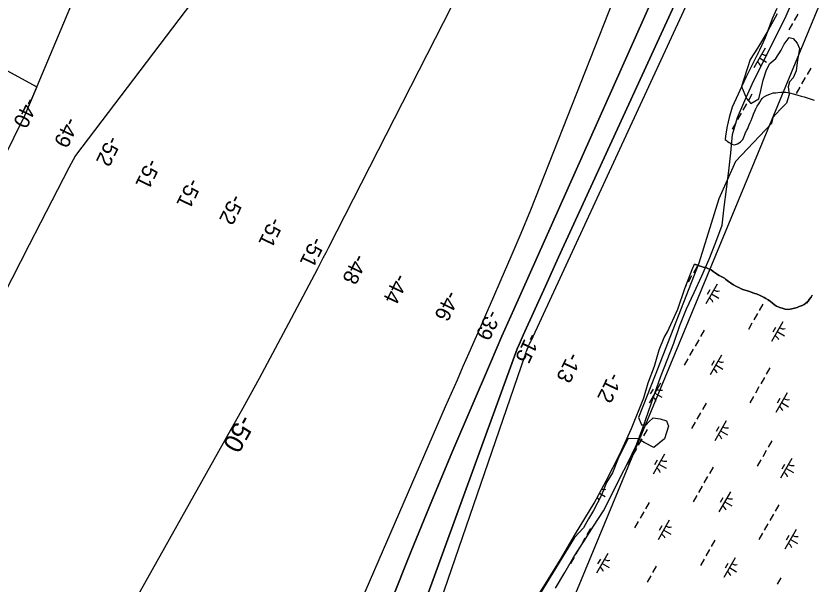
# Model space of a CAD drawing. Extents: x 3930721 to 3950824, y 220441 to 242861.
# Drawn here: x 3938420 to 3940167, y 225003 to 226251 of the extents above; entities that cross this region are included whole.
import ezdxf

# ---------------------------------------------------------------- set-up
doc = ezdxf.new("R2010")
doc.units = 0
for name, color, linetype in [('V-RIVR-EDGE', 7, 'Continuous'), ('V-RIVR-RANG', 7, 'Continuous'), ('V-RRAP-FSHR', 7, 'Continuous'), ('V-TOPO-DPTH', 7, 'Continuous'), ('V-TOPO-MAJR', 7, 'Continuous'), ('V-TOPO-MAJR-IDEN', 7, 'Continuous'), ('V-TOPO-MINR', 7, 'Continuous'), ('V-TOPO-SHOR', 7, 'Continuous'), ('V-UTIL-LINE', 7, 'Continuous'), ('V-WETL-SWMP', 7, 'Continuous')]:
    doc.layers.add(name, color=color, linetype=linetype)

msp = doc.modelspace()

# ---------------------------------------------------------------- linework, layer by layer
at = {"layer": 'V-RIVR-EDGE'}
msp.add_lwpolyline([(3940090.5, 226255.7), (3940070, 226217.9), (3940047.2, 226180.1), (3940031.4, 226154.9), (3940012.5, 226095.9), (3940023.6, 226069.9), (3940033, 226058.9), (3940050.3, 226069.1), (3940055, 226087.2), (3940059.8, 226110), (3940066.9, 226132.9), (3940074.7, 226146.3), (3940087.3, 226157.3), (3940099.1, 226175.4), (3940106.2, 226188.8), (3940117.2, 226203.7), (3940125.9, 226201.4), (3940134.5, 226191.1), (3940139.3, 226179.3), (3940134.5, 226148.6), (3940132.2, 226130.5), (3940125.9, 226114.8), (3940118, 226106.1), (3940114.9, 226095.1), (3940117.2, 226078.6), (3940110.9, 226059.7), (3940096.8, 226045.5), (3940081, 226028.2), (3940077.9, 226014.8), (3939999.2, 225931.4), (3939962.2, 225849.5), (3939918.9, 225707.8), (3939822.8, 225462.2), (3939786.6, 225369.3), (3939792.9, 225352.8), (3939803.2, 225352.8), (3939808.7, 225359.9), (3939818.1, 225368.5), (3939833.9, 225366.2), (3939848, 225361.5), (3939852, 225350.4), (3939843.3, 225322.1), (3939819.7, 225303.2), (3939798.4, 225314.2), (3939785.8, 225322.1), (3939763.8, 225322.9), (3939741.8, 225278.8), (3939729.2, 225247.3), (3939715.8, 225226.1), (3939704, 225196.9), (3939687.4, 225164.7), (3939676.4, 225146.6), (3939665.4, 225126.9), (3939645.7, 225105.6), (3939564.6, 224973.4)], dxfattribs=at)
at = {"layer": 'V-RRAP-FSHR'}
msp.add_lwpolyline([(3939604.4, 224994.7), (3939624.4, 225028.7), (3939644.5, 225063.3), (3939666.1, 225096.9), (3939687.8, 225130.6), (3939709.4, 225164.2), (3939727.8, 225199.7), (3939745.5, 225235.6), (3939763.2, 225271.4), (3939781, 225307.3), (3939795.2, 225344.6), (3939808.4, 225382.4), (3939821.6, 225420.1), (3939834.7, 225457.9), (3939848.9, 225495.3), (3939864, 225532.7), (3939877.3, 225570.8), (3939891.7, 225607.4), (3939908.3, 225643.8), (3939925, 225680.1), (3939941.2, 225716.7), (3939955.6, 225754.1), (3939969.6, 225791.4), (3939974.6, 225831.1), (3939979.5, 225870.8), (3939984.4, 225910.5), (3939988.8, 225950.3), (3939992.5, 225990.8), (3940003.7, 226028.2), (3940019.3, 226064.9), (3940035.5, 226101.4), (3940053.4, 226137.2), (3940071.4, 226172.9), (3940089.3, 226208.7), (3940107.2, 226244.4), (3940123.5, 226281)], dxfattribs=at)
at = {"layer": 'V-TOPO-DPTH'}
for points in [[(3938800.3, 226891.8), (3938439, 226031.3), (3937974.2, 225089.4)], [(3939105.4, 224799.2), (3939362.9, 225393), (3939375.8, 225422.6), (3939388.7, 225452.2), (3939401.6, 225481.7), (3939414.6, 225511.3), (3939427.6, 225540.8), (3939440.6, 225570.3), (3939453.5, 225599.9), (3939466.5, 225629.4), (3939485.1, 225671.9), (3939507.1, 225722.9), (3939528.6, 225774), (3939549.7, 225825.3), (3939570.3, 225876.8), (3939810.4, 226486.5)], [(3939105.4, 224799.2), (3939362.9, 225393), (3939375.8, 225422.6), (3939388.7, 225452.2), (3939401.6, 225481.7), (3939414.6, 225511.3), (3939427.6, 225540.8), (3939440.6, 225570.3), (3939453.5, 225599.9), (3939466.5, 225629.4), (3939485.1, 225671.9), (3939507.1, 225722.9), (3939528.6, 225774), (3939549.7, 225825.3), (3939570.3, 225876.8), (3939810.4, 226486.5)], [(3939914.9, 226384.5), (3939698.1, 225912.3), (3939668.9, 225848.7), (3939639.8, 225785), (3939610.7, 225721.2), (3939581.8, 225657.4), (3939533, 225549.7), (3939528.5, 225539.8), (3939524, 225529.8), (3939519.7, 225519.7), (3939183.5, 224595.7), (3939172.7, 224570.5), (3939161.8, 224545.3), (3938861.8, 223862.2), (3938847, 223828.5), (3938832.2, 223794.8), (3938819, 223764.4)], [(3938766.8, 223792.5), (3938950.3, 224222), (3938978.7, 224289.3), (3939006.6, 224356.7), (3939033.9, 224424.4), (3939060.9, 224492.3), (3939085.7, 224556), (3939099.8, 224592.2), (3939113.9, 224628.4), (3939127.8, 224664.7), (3939141.8, 224701), (3939199.5, 224852.2), (3939242.9, 224963.9), (3939287.2, 225075.3), (3939332.7, 225186.1), (3939379.1, 225296.5), (3939461.4, 225489.5), (3939474, 225518.8), (3939486.6, 225548), (3939499.4, 225577.1), (3939512.3, 225606.2), (3939815.8, 226284.8)], [(3939815.8, 226284.8), (3939512.3, 225606.2), (3939499.4, 225577.1), (3939486.6, 225548), (3939474, 225518.8), (3939461.4, 225489.5), (3939379.1, 225296.5), (3939332.7, 225186.1), (3939287.2, 225075.3), (3939242.9, 224963.9), (3939199.5, 224852.2), (3939141.8, 224701), (3939127.8, 224664.7), (3939113.9, 224628.4), (3939099.8, 224592.2), (3939085.7, 224556), (3939060.9, 224492.3), (3939033.9, 224424.4), (3939006.6, 224356.7), (3938978.7, 224289.3), (3938950.3, 224222), (3938766.8, 223792.5)], [(3938372.1, 226089.8), (3938383.8, 226098.3), (3938393.5, 226111.8), (3938400.2, 226131.1), (3938466, 226095.5)], [(3938466, 226095.5), (3938439, 226031.3), (3937974.2, 225089.4), (3937855.6, 224787.7), (3937817.1, 224692.8), (3937777.4, 224598.4), (3937735.8, 224504.8), (3937692.9, 224411.8), (3937676.9, 224378)]]:
    msp.add_lwpolyline(points, dxfattribs=at)
at = {"layer": 'V-TOPO-MAJR'}
for points in [[(3939076.2, 226636.5), (3938550.3, 225944.2), (3938535.9, 225917), (3938448.9, 225748.2), (3938391.7, 225636.2)], [(3938237.8, 224076.7), (3938466.6, 224557.2), (3938489.6, 224604.6), (3938512.9, 224651.9), (3938536.7, 224699), (3938560.8, 224745.8), (3938572.8, 224768.7), (3938591.4, 224803.9), (3938610.2, 224839), (3938629.3, 224873.9), (3938648.6, 224908.7), (3938882, 225325), (3938918.3, 225390.3), (3938954.3, 225455.8), (3938989.7, 225521.6), (3939024.8, 225587.5), (3939082.3, 225696.6), (3939088.4, 225708.2), (3939094.4, 225719.7), (3939100.4, 225731.3), (3939106.3, 225742.9), (3939376.3, 226272.7)]]:
    msp.add_lwpolyline(points, dxfattribs=at)
at = {"layer": 'V-TOPO-MINR'}
for points in [[(3938800.3, 226891.8), (3938439, 226031.3), (3937974.2, 225089.4)], [(3939105.4, 224799.2), (3939362.9, 225393), (3939375.8, 225422.6), (3939388.7, 225452.2), (3939401.6, 225481.7), (3939414.6, 225511.3), (3939427.6, 225540.8), (3939440.6, 225570.3), (3939453.5, 225599.9), (3939466.5, 225629.4), (3939485.1, 225671.9), (3939507.1, 225722.9), (3939528.6, 225774), (3939549.7, 225825.3), (3939570.3, 225876.8), (3939810.4, 226486.5)], [(3938819, 223764.4), (3938832.2, 223794.8), (3938847, 223828.5), (3938861.8, 223862.2), (3939161.8, 224545.3), (3939172.7, 224570.5), (3939183.5, 224595.7), (3939519.7, 225519.7), (3939524, 225529.8), (3939528.5, 225539.8), (3939533, 225549.7), (3939581.8, 225657.4), (3939610.7, 225721.2), (3939639.8, 225785), (3939668.9, 225848.7), (3939698.1, 225912.3), (3939914.9, 226384.5)], [(3939247.7, 224662.8), (3939536.9, 225503.8), (3939537.3, 225505.4), (3939538.1, 225508.6), (3939538.6, 225510.2), (3939539.7, 225513.4), (3939540.9, 225516.5), (3939542.7, 225520.7), (3939542.9, 225521.1), (3939543.1, 225521.6), (3939545.3, 225526.4), (3939546.6, 225529.2), (3939547.9, 225532), (3939549.2, 225534.9), (3939550.5, 225537.7), (3939926.9, 226351.3)], [(3938766.8, 223792.5), (3938950.3, 224222), (3938978.7, 224289.3), (3939006.6, 224356.7), (3939033.9, 224424.4), (3939060.9, 224492.3), (3939085.7, 224556), (3939099.8, 224592.2), (3939113.9, 224628.4), (3939127.8, 224664.7), (3939141.8, 224701), (3939199.5, 224852.2), (3939242.9, 224963.9), (3939287.2, 225075.3), (3939332.7, 225186.1), (3939379.1, 225296.5), (3939461.4, 225489.5), (3939474, 225518.8), (3939486.6, 225548), (3939499.4, 225577.1), (3939512.3, 225606.2), (3939815.8, 226284.8)]]:
    msp.add_lwpolyline(points, dxfattribs=at)
at = {"layer": 'V-TOPO-SHOR'}
for points in [[(3939976.2, 225979.8), (3939979.3, 225977.4), (3939981.9, 225975.4), (3939984.9, 225973), (3939988.4, 225971.2), (3939991.4, 225969.4), (3939995.9, 225968), (3939999.1, 225968.4), (3940003.8, 225970.1), (3940007.4, 225972.5), (3940009.8, 225974.4), (3940012.6, 225976.6), (3940015.1, 225979.4), (3940017.3, 225984.7), (3940019.6, 225990.6), (3940021.4, 225994.8), (3940024.3, 226000.1), (3940025.9, 226003.4), (3940027.9, 226008.2), (3940029.2, 226011.5), (3940031.6, 226017.2), (3940033.4, 226021), (3940035.4, 226027.1), (3940037.2, 226031.1), (3940038.8, 226035.4), (3940041.8, 226042.1), (3940043.6, 226046.6), (3940047, 226052.8), (3940050, 226058.1), (3940052.2, 226061.8), (3940055.5, 226066.8), (3940057.7, 226069.5), (3940060.3, 226072.3), (3940065.5, 226075.6), (3940068.8, 226077), (3940074.2, 226079.3), (3940078, 226080.7), (3940081.9, 226081.8), (3940087.7, 226082.4), (3940091.8, 226082.8), (3940098.5, 226083.5), (3940103.1, 226083.5), (3940109.6, 226083.3), (3940114, 226082.5), (3940120.3, 226081.2), (3940125.4, 226079.6), (3940133.9, 226077.6), (3940143, 226075), (3940149.7, 226073.2), (3940156.6, 226071.2), (3940163.1, 226069), (3940172, 226065.6)], [(3940167.3, 225637.6), (3940164.9, 225633.3), (3940160.9, 225628.2), (3940158.3, 225624.8), (3940153.6, 225620.3), (3940149.8, 225617.5), (3940145.6, 225615.2), (3940139.1, 225612.6), (3940134.7, 225610.7), (3940128.6, 225608.9), (3940122.6, 225607.4), (3940118.9, 225606.8), (3940114.7, 225606.6), (3940108.2, 225607.1), (3940103.5, 225608.3), (3940096.2, 225610.7), (3940089.3, 225613.7), (3940084.9, 225616.5), (3940079.4, 225621.1), (3940075.9, 225624), (3940071.1, 225627.4), (3940065.6, 225630.6), (3940062.1, 225632.6), (3940056.3, 225635.6), (3940051.6, 225638), (3940048.1, 225639.4), (3940045.1, 225640.6), (3940041.9, 225641.4), (3940037, 225643.2), (3940031.7, 225644.8), (3940025.2, 225647), (3940020.4, 225648.5), (3940017.1, 225649.7), (3940011.7, 225651.9), (3940006.6, 225654.3), (3940002.9, 225655.7), (3939999.5, 225657.7), (3939994.4, 225660.5), (3939991, 225662.6), (3939987.9, 225664.8), (3939983.7, 225668), (3939981, 225669.8), (3939977.2, 225673), (3939974.7, 225675), (3939970.5, 225677.6), (3939967.6, 225679), (3939963.4, 225681.2), (3939959.7, 225683.2), (3939954.2, 225686.8), (3939950, 225689.4), (3939945.9, 225693.1), (3939942.4, 225694.9), (3939938.4, 225696.5), (3939935.5, 225697.5), (3939932.1, 225698.5), (3939928.5, 225699.6), (3939924.8, 225700.8), (3939919.5, 225702.4), (3939915.9, 225703.6), (3939908.9, 225706.1)]]:
    msp.add_lwpolyline(points, dxfattribs=at)
at = {"layer": 'V-UTIL-LINE'}
msp.add_lwpolyline([(3947453.8, 235874.4), (3945931.1, 235655.1), (3945509.1, 234777.7), (3940428.6, 226869.1), (3939084.6, 223621.7)], dxfattribs=at)
at = {"layer": 'V-WETL-SWMP'}
for p, q in [((3940136.1, 226255), (3940128.2, 226241.1)), ((3940124.2, 226234.2), (3940116.3, 226220.3)), ((3940064.1, 226180.2), (3940039.3, 226136.9)), ((3940048, 226167.6), (3940047.4, 226166.5)), ((3940051.7, 226158.6), (3940067.3, 226149.6)), ((3940164.2, 226136.4), (3940156.2, 226122.5)), ((3940152.2, 226115.6), (3940144.3, 226101.7)), ((3940140.3, 226094.8), (3940132.4, 226080.9)), ((3940035.3, 226078.9), (3940027.3, 226065)), ((3940023.3, 226058), (3940015.4, 226044.2)), ((3940011.4, 226037.2), (3940003.5, 226023.3)), ((3939999.5, 226016.4), (3939991.5, 226002.5)), ((3939887.9, 225652.3), (3939904.2, 225693.8)), ((3939904.2, 225693.8), (3939908.9, 225706.1)), ((3939914.7, 225700.9), (3939906.8, 225687)), ((3939908.9, 225706.1), (3939915.9, 225703.6)), ((3939915.9, 225703.6), (3939919.5, 225702.4)), ((3939919.5, 225702.4), (3939924.8, 225700.8)), ((3939924.8, 225700.8), (3939928.5, 225699.6)), ((3939928.5, 225699.6), (3939932.1, 225698.5)), ((3939932.1, 225698.5), (3939935.6, 225697.5)), ((3939935.6, 225697.5), (3939938.4, 225696.5)), ((3939938.4, 225696.5), (3939942.4, 225694.9)), ((3939942.4, 225694.9), (3939945.9, 225693.1)), ((3939945.9, 225693.1), (3939950, 225689.4)), ((3939950, 225689.4), (3939954.2, 225686.8)), ((3939902.8, 225680.1), (3939894.9, 225666.2)), ((3939954.2, 225686.8), (3939959.7, 225683.2)), ((3939959.7, 225683.2), (3939963.4, 225681.2)), ((3939963.4, 225681.2), (3939967.6, 225679)), ((3939967.6, 225679), (3939970.5, 225677.6)), ((3939970.5, 225677.6), (3939974.7, 225675)), ((3939974.7, 225675), (3939977.2, 225673)), ((3939977.2, 225673), (3939981, 225669.8)), ((3939890.9, 225659.2), (3939890, 225657.7)), ((3939959, 225662), (3939934.2, 225618.7)), ((3939981, 225669.8), (3939983.7, 225668)), ((3939983.7, 225668), (3939987.9, 225664.8)), ((3939987.9, 225664.8), (3939991, 225662.6)), ((3939991, 225662.6), (3939994.4, 225660.5)), ((3939994.4, 225660.5), (3939999.5, 225657.7)), ((3939999.5, 225657.7), (3940002.9, 225655.7)), ((3940002.9, 225655.7), (3940006.6, 225654.3)), ((3940006.6, 225654.3), (3940011.7, 225651.9)), ((3939872.7, 225606.7), (3939887.9, 225652.3)), ((3939942.9, 225649.4), (3939936.9, 225639)), ((3939946.6, 225640.4), (3939962.2, 225631.4)), ((3940011.7, 225651.9), (3940017.1, 225649.7)), ((3940017.1, 225649.7), (3940020.4, 225648.5)), ((3940020.4, 225648.5), (3940025.2, 225647)), ((3940025.2, 225647), (3940031.7, 225644.8)), ((3940031.7, 225644.8), (3940037, 225643.2)), ((3940037, 225643.2), (3940041.9, 225641.4)), ((3940041.9, 225641.4), (3940045.1, 225640.6)), ((3940045.1, 225640.6), (3940048.1, 225639.4)), ((3940048.1, 225639.4), (3940051.6, 225638)), ((3940051.6, 225638), (3940056.3, 225635.6)), ((3940164.9, 225633.3), (3940167.3, 225637.6)), ((3940056.3, 225635.6), (3940062.1, 225632.6)), ((3940062.1, 225632.6), (3940065.6, 225630.6)), ((3940065.6, 225630.6), (3940071.1, 225627.4)), ((3940071.1, 225627.4), (3940075.9, 225624)), ((3940075.9, 225624), (3940079.4, 225621.1)), ((3940079.4, 225621.1), (3940084.9, 225616.5)), ((3940149.8, 225617.5), (3940153.6, 225620.3)), ((3940153.6, 225620.3), (3940158.3, 225624.8)), ((3940159.6, 225626.5), (3940155.5, 225619.4)), ((3940158.3, 225624.8), (3940160.9, 225628.2)), ((3940160.9, 225628.2), (3940164.9, 225633.3)), ((3939849.7, 225557), (3939872.7, 225606.7)), ((3940059.1, 225618.2), (3940051.1, 225604.3)), ((3940084.9, 225616.5), (3940089.3, 225613.7)), ((3940089.3, 225613.7), (3940096.2, 225610.7)), ((3940096.2, 225610.7), (3940103.5, 225608.3)), ((3940103.5, 225608.3), (3940108.2, 225607.1)), ((3940108.2, 225607.1), (3940114.7, 225606.6)), ((3940114.7, 225606.6), (3940118.9, 225606.8)), ((3940118.9, 225606.8), (3940122.6, 225607.4)), ((3940122.6, 225607.4), (3940128.6, 225608.9)), ((3940128.6, 225608.9), (3940134.7, 225610.7)), ((3940134.7, 225610.7), (3940139.1, 225612.6)), ((3940139.1, 225612.6), (3940145.6, 225615.2)), ((3940145.6, 225615.2), (3940149.8, 225617.5)), ((3940047.2, 225597.4), (3940039.2, 225583.5)), ((3940035.2, 225576.6), (3940027.3, 225562.7)), ((3940103.3, 225579.4), (3940078.5, 225536)), ((3939842.3, 225544.6), (3939849.7, 225557)), ((3939930.2, 225560.7), (3939922.2, 225546.8)), ((3940087.2, 225566.7), (3940081.2, 225556.3)), ((3940090.9, 225557.7), (3940106.5, 225548.7)), ((3939831.9, 225517.4), (3939842.3, 225544.6)), ((3939918.3, 225539.8), (3939910.3, 225526)), ((3939821, 225482), (3939831.9, 225517.4)), ((3939906.3, 225519), (3939898.4, 225505.1)), ((3939894.4, 225498.2), (3939886.4, 225484.3)), ((3939968.2, 225506.2), (3939943.3, 225462.8)), ((3939807.8, 225445.1), (3939821, 225482)), ((3939952, 225493.5), (3939946.1, 225483.1)), ((3939955.7, 225484.5), (3939971.3, 225475.5)), ((3940074.5, 225478), (3940066.6, 225464.1)), ((3939797.9, 225412.2), (3939807.8, 225445.1)), ((3940062.6, 225457.2), (3940054.6, 225443.3)), ((3939834.3, 225444.3), (3939809.4, 225400.9)), ((3939818.1, 225431.6), (3939812.2, 225421.2)), ((3940050.7, 225436.3), (3940042.7, 225422.5)), ((3939770.7, 225345.3), (3939797.9, 225412.2)), ((3939821.9, 225422.6), (3939837.5, 225413.6)), ((3940038.7, 225415.5), (3940030.8, 225401.6)), ((3940112.5, 225423.5), (3940087.6, 225380.1)), ((3940096.4, 225410.8), (3940090.4, 225400.4)), ((3939934.4, 225400.5), (3939926.4, 225386.6)), ((3940100.1, 225401.8), (3940115.7, 225392.9)), ((3939922.4, 225379.6), (3939914.5, 225365.7)), ((3939910.5, 225358.8), (3939902.6, 225344.9)), ((3939978.6, 225361.6), (3939953.8, 225318.2)), ((3939745.1, 225288.5), (3939770.7, 225345.3)), ((3939805.5, 225342.9), (3939797.5, 225329)), ((3939962.5, 225349), (3939956.5, 225338.5)), ((3939966.2, 225339.9), (3939981.8, 225331)), ((3939793.5, 225322.1), (3939785.6, 225308.2)), ((3940078.7, 225317.8), (3940070.8, 225303.9)), ((3939715.4, 225229.9), (3939745.1, 225288.5)), ((3939781.6, 225301.2), (3939773.7, 225287.4)), ((3939843.4, 225288.4), (3939818.6, 225245)), ((3940066.8, 225297), (3940058.8, 225283.1)), ((3939769.7, 225280.4), (3939761.7, 225266.5)), ((3939827.3, 225275.7), (3939821.3, 225265.3)), ((3940054.8, 225276.1), (3940046.9, 225262.2)), ((3940123, 225278.9), (3940098.1, 225235.6)), ((3939831, 225266.7), (3939846.6, 225257.8)), ((3939949.8, 225260.2), (3939941.9, 225246.3)), ((3940106.8, 225266.3), (3940100.9, 225255.9)), ((3940110.5, 225257.3), (3940126.2, 225248.3)), ((3939937.9, 225239.4), (3939929.9, 225225.5)), ((3939688.8, 225180.8), (3939715.4, 225229.9)), ((3939926, 225218.6), (3939918, 225204.7)), ((3939700.7, 225202.8), (3939712.8, 225195.9)), ((3939987.8, 225205.7), (3939962.9, 225162.3)), ((3939809.6, 225182.7), (3939801.7, 225168.8)), ((3939914, 225197.8), (3939906.1, 225183.9)), ((3939971.6, 225193.1), (3939965.7, 225182.7)), ((3939975.4, 225184), (3939991, 225175.1)), ((3939648.1, 225113.6), (3939688.8, 225180.8)), ((3940094.1, 225177.6), (3940086.2, 225163.7)), ((3939797.7, 225161.9), (3939789.8, 225148)), ((3940082.2, 225156.7), (3940074.3, 225142.9)), ((3939785.8, 225141), (3939777.8, 225127.1)), ((3939853.9, 225143.8), (3939829.1, 225100.5)), ((3939837.8, 225131.2), (3939831.8, 225120.8)), ((3940070.3, 225135.9), (3940062.3, 225122)), ((3939615.2, 225057.2), (3939648.1, 225113.6)), ((3939680.7, 225125.1), (3939672.8, 225111.2)), ((3939841.5, 225122.1), (3939857.1, 225113.2)), ((3940058.4, 225115.1), (3940050.4, 225101.2)), ((3940132.1, 225123.1), (3940107.3, 225079.7)), ((3939668.8, 225104.3), (3939660.9, 225090.4)), ((3939954, 225100), (3939946, 225086.1)), ((3940116, 225110.4), (3940110, 225100)), ((3940119.7, 225101.4), (3940135.3, 225092.4)), ((3939656.9, 225083.5), (3939648.9, 225069.6)), ((3939942.1, 225079.2), (3939934.1, 225065.3)), ((3939645, 225062.7), (3939637, 225048.8)), ((3939718.7, 225070.6), (3939693.9, 225027.2)), ((3939998.3, 225061.2), (3939973.4, 225017.8)), ((3939582.3, 225004.2), (3939615.2, 225057.2)), ((3939702.6, 225058), (3939696.6, 225047.6)), ((3939706.3, 225048.9), (3939721.9, 225040)), ((3939930.1, 225058.4), (3939922.2, 225044.5)), ((3939982.1, 225048.5), (3939976.1, 225038.1)), ((3939825.1, 225042.5), (3939817.1, 225028.6)), ((3939985.8, 225039.5), (3940001.4, 225030.5)), ((3939813.2, 225021.6), (3939805.2, 225007.8)), ((3940098.3, 225017.3), (3940090.4, 225003.5)), ((3939559, 224967.1), (3939582.3, 225004.2))]:
    msp.add_line(p, q, dxfattribs=at)
for points in [[(3940090.2, 226266.9), (3940079.6, 226244.4), (3940064.6, 226202.5), (3940052, 226175.7), (3940021.6, 226115.7), (3939991.6, 226050.6), (3939985, 226027.7), (3939981.1, 226009.2), (3939977.5, 225987.4), (3939976.2, 225979.8), (3939979.3, 225977.4), (3939981.9, 225975.4), (3939984.9, 225973), (3939988.4, 225971.2), (3939991.4, 225969.4), (3939995.9, 225968), (3939999.1, 225968.4), (3940003.8, 225970.1), (3940007.4, 225972.5)], [(3940007.4, 225972.5), (3940009.8, 225974.4), (3940012.6, 225976.6), (3940015.1, 225979.4), (3940017.3, 225984.7), (3940019.6, 225990.6), (3940021.4, 225994.8), (3940024.3, 226000.1), (3940025.9, 226003.4), (3940027.9, 226008.2), (3940029.2, 226011.5), (3940031.6, 226017.2), (3940033.4, 226021), (3940035.4, 226027.1), (3940037.2, 226031.1), (3940038.8, 226035.4), (3940041.8, 226042.1), (3940043.6, 226046.6), (3940047, 226052.8), (3940050, 226058.1), (3940052.2, 226061.8), (3940055.5, 226066.8), (3940057.7, 226069.5), (3940060.3, 226072.3), (3940065.5, 226075.6), (3940068.8, 226077), (3940074.2, 226079.3), (3940078, 226080.7), (3940081.9, 226081.8), (3940087.7, 226082.4), (3940091.8, 226082.8), (3940098.5, 226083.5), (3940103.1, 226083.5), (3940109.6, 226083.3), (3940114, 226082.5), (3940120.3, 226081.2), (3940125.4, 226079.6), (3940133.9, 226077.6), (3940143, 226075), (3940149.7, 226073.2), (3940156.6, 226071.2), (3940163.1, 226069), (3940172, 226065.6)]]:
    msp.add_lwpolyline(points, dxfattribs=at)
for centre, start, end in [((3940065.6, 226182.4), 239.4279, 280.9715), ((3940038.2, 226134.5), 19.4279, 60.9715), ((3939960.5, 225664.2), 239.4279, 280.9715), ((3939933.1, 225616.3), 19.4279, 60.9715), ((3940104.9, 225581.5), 239.4279, 280.9715), ((3940077.4, 225533.6), 19.4279, 60.9715), ((3939969.7, 225508.3), 239.4279, 280.9715), ((3939942.2, 225460.4), 19.4279, 60.9715), ((3939835.8, 225446.4), 239.4279, 280.9715), ((3939808.3, 225398.5), 19.4279, 60.9715), ((3940114, 225425.7), 239.4279, 280.9715), ((3940086.5, 225377.7), 19.4279, 60.9715), ((3939980.1, 225363.8), 239.4279, 280.9715), ((3939952.7, 225315.8), 19.4279, 60.9715), ((3939844.9, 225290.6), 239.4279, 280.9715), ((3939817.5, 225242.6), 19.4279, 60.9715), ((3940124.5, 225281.1), 239.4279, 280.9715), ((3940097, 225233.2), 19.4279, 60.9715), ((3939711.1, 225228.7), 252.1766, 280.9715), ((3939683.6, 225180.7), 19.4279, 46.6306), ((3939989.3, 225207.9), 239.4279, 280.9715), ((3939961.8, 225160), 19.4279, 60.9715), ((3939855.4, 225146), 239.4279, 280.9715), ((3939828, 225098.1), 19.4279, 60.9715), ((3940133.6, 225125.2), 239.4279, 280.9715), ((3940106.2, 225077.3), 19.4279, 60.9715), ((3939720.2, 225072.8), 239.4279, 280.9715), ((3939999.8, 225063.3), 239.4279, 280.9715), ((3939692.8, 225024.8), 19.4279, 60.9715), ((3939972.3, 225015.4), 19.4279, 60.9715)]:
    msp.add_arc(centre, 17.6, start, end, dxfattribs=at)

# ---------------------------------------------------------------- texts
at = {"layer": 'V-RIVR-RANG'}
for s, rotation, p in [('-40', 244.0695, (3938441.3, 226074.2)), ('-49', 244.0695, (3938530.6, 226031.1)), ('-52', 244.0695, (3938622.9, 225990)), ('-51', 244.0695, (3938709.5, 225939.7)), ('-51', 244.0695, (3938799.6, 225896.9)), ('-52', 244.0695, (3938893.2, 225861.6)), ('-51', 244.0695, (3938979.5, 225811.3)), ('-51', 244.0695, (3939070.4, 225768.1)), ('-48', 244.0695, (3939163.6, 225730.7)), ('-44', 244.0695, (3939253.5, 225687.5)), ('-46', 243.9283, (3939365.9, 225650.2)), ('-39', 243.9283, (3939456.6, 225608.1)), ('-15', 243.9283, (3939543.1, 225557.3)), ('-13', 243.9283, (3939633.4, 225514.3)), ('-12', 243.9283, (3939723.2, 225470.4))]:
    msp.add_text(s, height=33.5, rotation=rotation, dxfattribs=at).set_placement(p)
at = {"layer": 'V-TOPO-MAJR-IDEN'}
msp.add_text('-50', height=41.5, rotation=240.9457, dxfattribs=at).set_placement((3938911.6, 225378.3))

doc.saveas('drawing.dxf')
